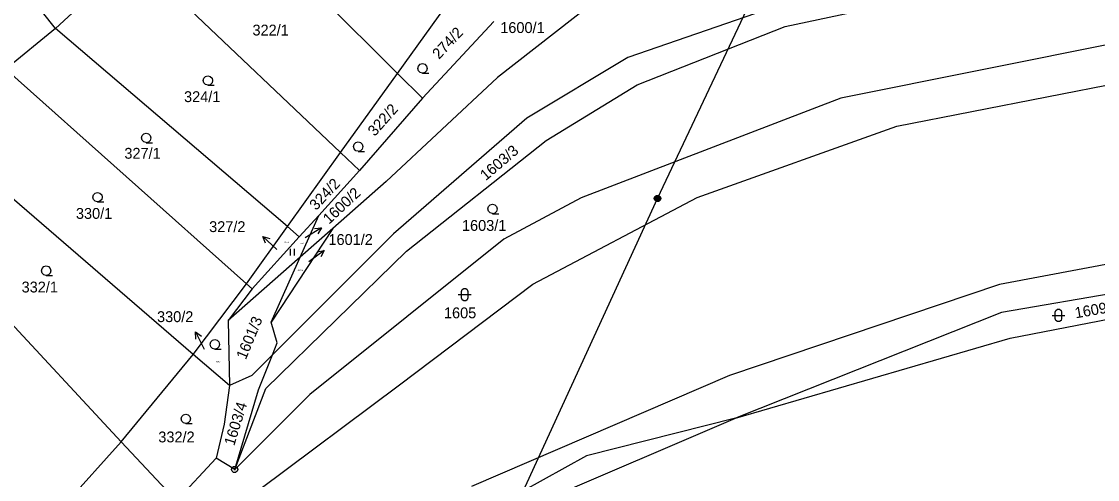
# Model space of a CAD drawing. Extents: x -609861 to -605046, y -1120287 to -1116307.
# Drawn here: x -607005 to -606836.4, y -1119419.2 to -1119347.5 of the extents above; entities that cross this region are included whole.
import ezdxf

# ---------------------------------------------------------------- set-up
doc = ezdxf.new("R2010")
doc.units = 0
for name, color, linetype in [('Vrstva 1', 7, 'Continuous'), ('Vrstva 2', 7, 'Continuous'), ('Vrstva 3', 7, 'Continuous'), ('Vrstva 6', 7, 'Continuous'), ('Vrstva 7', 7, 'Continuous'), ('Vrstva 8', 7, 'Continuous')]:
    doc.layers.add(name, color=color, linetype=linetype)

msp = doc.modelspace()

# ---------------------------------------------------------------- linework, layer by layer
at = {"layer": 'Vrstva 1'}
for p, q in [((-606946.12, -1119355.62), (-606977.36, -1119324.47)), ((-606955.04, -1119368.04), (-606988.81, -1119335.87)), ((-606989.19, -1119338.85), (-606999.69, -1119348.61)), ((-606885.36, -1119348.3), (-606850.68, -1119340.86)), ((-606999.69, -1119348.61), (-607004.74, -1119342.23)), ((-606946.12, -1119355.62), (-606935.93, -1119341.43)), ((-606915.48, -1119344.63), (-606930.45, -1119356.29)), ((-606888.5, -1119345.74), (-606910.04, -1119353.16)), ((-606931.04, -1119347.49), (-606942.21, -1119359.52)), ((-606999.69, -1119348.61), (-607007.45, -1119354.95)), ((-606963.35, -1119379.63), (-606999.69, -1119348.61)), ((-606908.56, -1119357.42), (-606885.36, -1119348.3)), ((-606831.75, -1119350.51), (-606876.64, -1119359.5)), ((-606910.04, -1119353.16), (-606925.84, -1119362.66)), ((-606969.76, -1119388.57), (-607007.45, -1119354.95)), ((-606955.04, -1119368.04), (-606946.12, -1119355.62)), ((-606942.21, -1119359.52), (-606946.12, -1119355.62)), ((-606930.45, -1119356.29), (-606947.9, -1119372.58)), ((-606922.81, -1119366.13), (-606908.56, -1119357.42)), ((-606867.87, -1119363.9), (-606830.79, -1119356.66)), ((-606942.21, -1119359.52), (-606952.08, -1119370.86)), ((-606876.64, -1119359.5), (-606917.32, -1119375.11)), ((-606925.84, -1119362.66), (-606946.75, -1119380.73)), ((-606899.18, -1119375.06), (-606867.87, -1119363.9)), ((-606978.11, -1119399.64), (-607018.21, -1119365.11)), ((-606944.72, -1119383.49), (-606922.81, -1119366.13)), ((-606963.35, -1119379.63), (-606955.04, -1119368.04)), ((-606952.08, -1119370.86), (-606955.04, -1119368.04)), ((-606952.08, -1119370.86), (-606958.46, -1119377.87)), ((-606947.9, -1119372.58), (-606956.23, -1119379.91)), ((-606989.38, -1119413.31), (-607025.73, -1119374.26)), ((-606917.32, -1119375.11), (-606929.46, -1119381.58)), ((-606924.91, -1119388.66), (-606899.18, -1119375.06)), ((-606958.46, -1119377.87), (-606961.5, -1119381.2)), ((-606961.37, -1119384.43), (-606958.46, -1119377.87)), ((-606969.76, -1119388.57), (-606963.35, -1119379.63)), ((-606961.5, -1119381.2), (-606963.35, -1119379.63)), ((-606801.93, -1119379.31), (-606851.78, -1119388.68)), ((-606961.5, -1119381.2), (-606968.89, -1119389.35)), ((-606956.23, -1119379.91), (-606965.88, -1119394.61)), ((-606946.75, -1119380.73), (-606965.7, -1119399.71)), ((-606956.23, -1119379.91), (-606961.37, -1119384.43)), ((-606929.46, -1119381.58), (-606959.85, -1119405.9)), ((-606961.37, -1119384.43), (-606972.62, -1119394.33)), ((-606966.74, -1119404.96), (-606944.72, -1119383.49)), ((-606965.88, -1119394.61), (-606961.37, -1119384.43)), ((-606812.23, -1119386.28), (-606851.48, -1119393.09)), ((-606850.14, -1119397.08), (-606796.64, -1119386.74)), ((-606978.11, -1119399.64), (-606969.76, -1119388.57)), ((-606968.89, -1119389.35), (-606972.62, -1119394.33)), ((-606968.89, -1119389.35), (-606969.76, -1119388.57)), ((-606945.8, -1119404.38), (-606924.91, -1119388.66)), ((-606851.78, -1119388.68), (-606894.11, -1119402.92)), ((-606851.48, -1119393.09), (-606893.15, -1119409.63)), ((-606972.62, -1119394.33), (-606972.44, -1119404.52)), ((-606964.95, -1119397.81), (-606965.88, -1119394.61)), ((-606965.7, -1119399.71), (-606964.95, -1119397.81)), ((-606893.15, -1119409.63), (-606850.14, -1119397.08)), ((-606989.38, -1119413.31), (-606978.11, -1119399.64)), ((-606972.44, -1119404.52), (-606978.11, -1119399.64)), ((-606965.7, -1119399.71), (-606968.93, -1119402.94)), ((-606967.87, -1119405.18), (-606965.7, -1119399.71)), ((-606968.93, -1119402.94), (-606972.44, -1119404.52)), ((-606894.11, -1119402.92), (-606934.5, -1119420.33)), ((-606972.44, -1119404.52), (-606973.28, -1119410.57)), ((-606967.9, -1119420.89), (-606945.8, -1119404.38)), ((-606971.62, -1119417.67), (-606966.74, -1119404.96)), ((-606971.62, -1119417.67), (-606967.87, -1119405.18)), ((-606959.85, -1119405.9), (-606971.62, -1119417.67)), ((-606923.77, -1119422.74), (-606893.15, -1119409.63)), ((-606893.15, -1119409.63), (-606916.49, -1119415.51)), ((-606973.28, -1119410.57), (-606974.51, -1119415.91)), ((-607001.13, -1119426.36), (-606989.38, -1119413.31)), ((-606980.75, -1119422.57), (-606989.38, -1119413.31)), ((-606974.51, -1119415.91), (-606980.75, -1119422.57)), ((-606971.62, -1119417.67), (-606974.51, -1119415.91)), ((-606916.49, -1119415.51), (-606965.86, -1119442.76))]:
    msp.add_line(p, q, dxfattribs=at)
at = {"layer": 'Vrstva 3'}
for p, q in [((-606962.94, -1119383.09), (-606962.94, -1119384.14)), ((-606962.24, -1119384.14), (-606962.24, -1119383.09))]:
    msp.add_line(p, q, dxfattribs=at)
for points in [[(-606942.18, -1119355.58), (-606942.56, -1119355.48), (-606942.83, -1119355.21), (-606942.93, -1119354.84), (-606942.83, -1119354.47), (-606942.56, -1119354.2), (-606942.19, -1119354.1), (-606941.82, -1119354.2), (-606941.55, -1119354.47), (-606941.45, -1119354.85), (-606941.55, -1119355.23), (-606941.82, -1119355.5), (-606942.2, -1119355.6), (-606941.2, -1119355.6)], [(-606975.8, -1119357.47), (-606976.18, -1119357.37), (-606976.45, -1119357.1), (-606976.55, -1119356.73), (-606976.45, -1119356.36), (-606976.18, -1119356.09), (-606975.81, -1119355.99), (-606975.44, -1119356.09), (-606975.17, -1119356.36), (-606975.07, -1119356.74), (-606975.17, -1119357.12), (-606975.44, -1119357.39), (-606975.82, -1119357.49), (-606974.82, -1119357.49)], [(-606985.49, -1119366.46), (-606985.87, -1119366.36), (-606986.14, -1119366.09), (-606986.24, -1119365.72), (-606986.14, -1119365.35), (-606985.87, -1119365.08), (-606985.5, -1119364.98), (-606985.13, -1119365.08), (-606984.86, -1119365.35), (-606984.76, -1119365.73), (-606984.86, -1119366.11), (-606985.13, -1119366.38), (-606985.51, -1119366.48), (-606984.51, -1119366.48)], [(-606952.25, -1119367.83), (-606952.63, -1119367.73), (-606952.9, -1119367.46), (-606953, -1119367.09), (-606952.9, -1119366.72), (-606952.63, -1119366.45), (-606952.26, -1119366.35), (-606951.89, -1119366.45), (-606951.62, -1119366.72), (-606951.52, -1119367.1), (-606951.62, -1119367.48), (-606951.89, -1119367.75), (-606952.27, -1119367.85), (-606951.27, -1119367.85)], [(-606993.09, -1119375.74), (-606993.47, -1119375.64), (-606993.74, -1119375.37), (-606993.84, -1119375), (-606993.74, -1119374.63), (-606993.47, -1119374.36), (-606993.1, -1119374.26), (-606992.73, -1119374.36), (-606992.46, -1119374.63), (-606992.36, -1119375.01), (-606992.46, -1119375.39), (-606992.73, -1119375.66), (-606993.11, -1119375.76), (-606992.11, -1119375.76)], [(-606931.22, -1119377.59), (-606931.6, -1119377.49), (-606931.87, -1119377.22), (-606931.97, -1119376.85), (-606931.87, -1119376.48), (-606931.6, -1119376.21), (-606931.23, -1119376.11), (-606930.86, -1119376.21), (-606930.59, -1119376.48), (-606930.49, -1119376.86), (-606930.59, -1119377.24), (-606930.86, -1119377.51), (-606931.24, -1119377.61), (-606930.24, -1119377.61)], [(-607001.14, -1119387.27), (-607001.52, -1119387.17), (-607001.79, -1119386.9), (-607001.89, -1119386.53), (-607001.79, -1119386.16), (-607001.52, -1119385.89), (-607001.15, -1119385.79), (-607000.78, -1119385.89), (-607000.51, -1119386.16), (-607000.41, -1119386.54), (-607000.51, -1119386.92), (-607000.78, -1119387.19), (-607001.16, -1119387.29), (-607000.16, -1119387.29)], [(-606936.58, -1119390.28), (-606935.31, -1119390.28), (-606934.58, -1119390.28)], [(-606843.56, -1119393.54), (-606842.29, -1119393.54), (-606841.56, -1119393.54)], [(-606974.71, -1119398.8), (-606975.09, -1119398.7), (-606975.36, -1119398.43), (-606975.46, -1119398.06), (-606975.36, -1119397.69), (-606975.09, -1119397.42), (-606974.72, -1119397.32), (-606974.35, -1119397.42), (-606974.08, -1119397.69), (-606973.98, -1119398.07), (-606974.08, -1119398.45), (-606974.35, -1119398.72), (-606974.73, -1119398.82), (-606973.73, -1119398.82)], [(-606979.27, -1119410.46), (-606979.65, -1119410.36), (-606979.92, -1119410.09), (-606980.02, -1119409.72), (-606979.92, -1119409.35), (-606979.65, -1119409.08), (-606979.28, -1119408.98), (-606978.91, -1119409.08), (-606978.64, -1119409.35), (-606978.54, -1119409.73), (-606978.64, -1119410.11), (-606978.91, -1119410.38), (-606979.29, -1119410.48), (-606978.29, -1119410.48)]]:
    msp.add_lwpolyline(points, dxfattribs=at)
for points in [[(-606936.08, -1119389.78), (-606935.98, -1119389.49), (-606935.73, -1119389.31), (-606935.42, -1119389.31), (-606935.17, -1119389.49), (-606935.07, -1119389.78), (-606935.07, -1119390.78), (-606935.17, -1119391.07), (-606935.42, -1119391.25), (-606935.73, -1119391.25), (-606935.98, -1119391.07), (-606936.08, -1119390.78)], [(-606843.06, -1119393.04), (-606842.96, -1119392.75), (-606842.71, -1119392.57), (-606842.4, -1119392.57), (-606842.15, -1119392.75), (-606842.05, -1119393.04), (-606842.05, -1119394.04), (-606842.15, -1119394.33), (-606842.4, -1119394.51), (-606842.71, -1119394.51), (-606842.96, -1119394.33), (-606843.06, -1119394.04)]]:
    msp.add_lwpolyline(points, close=True, dxfattribs=at)
at = {"layer": 'Vrstva 6'}
for p, q in [((-606905.37, -1119375.22), (-606885.51, -1119333.21)), ((-606927.27, -1119422.87), (-606905.37, -1119375.22))]:
    msp.add_line(p, q, dxfattribs=at)
msp.add_lwpolyline([(-606905.52, -1119374.74), (-606905.21, -1119374.74), (-606904.96, -1119374.92), (-606904.86, -1119375.21), (-606904.96, -1119375.5), (-606905.21, -1119375.68), (-606905.52, -1119375.68), (-606905.77, -1119375.5), (-606905.87, -1119375.21), (-606905.77, -1119374.92), (-606905.52, -1119374.74), (-606905.49, -1119374.78), (-606905.25, -1119374.78), (-606905.09, -1119374.86), (-606905.65, -1119374.86), (-606905.73, -1119374.94), (-606905.01, -1119374.94), (-606905.01, -1119375.02), (-606905.73, -1119375.02), (-606905.77, -1119375.1), (-606904.97, -1119375.1), (-606904.93, -1119375.18), (-606905.81, -1119375.18), (-606905.81, -1119375.26), (-606904.93, -1119375.26), (-606904.96, -1119375.34), (-606905.77, -1119375.34), (-606905.76, -1119375.42), (-606904.95, -1119375.42), (-606905, -1119375.5), (-606905.72, -1119375.5), (-606905.64, -1119375.58), (-606905.08, -1119375.58), (-606905.19, -1119375.66), (-606905.53, -1119375.66)], dxfattribs=at)
at = {"layer": 'Vrstva 7'}
for p, q in [((-606967.192, -1119381.152), (-606964.99, -1119383.19)), ((-606958.007, -1119379.795), (-606960.56, -1119381.37)), ((-606957.618, -1119383.352), (-606960.02, -1119385.15)), ((-606977.739, -1119396.125), (-606976.38, -1119398.8))]:
    msp.add_line(p, q, dxfattribs=at)
for points in [[(-606966.797, -1119382.198), (-606967.192, -1119381.152), (-606966.118, -1119381.464)], [(-606959.12, -1119379.895), (-606958.007, -1119379.795), (-606958.595, -1119380.746)], [(-606958.719, -1119383.551), (-606957.618, -1119383.352), (-606958.119, -1119384.352)], [(-606977.732, -1119397.243), (-606977.739, -1119396.125), (-606976.84, -1119396.79)]]:
    msp.add_lwpolyline(points, dxfattribs=at)
at = {"layer": 'Vrstva 8'}
msp.add_line((-606971.74, -1119417.67), (-606971.5, -1119417.67), dxfattribs=at)
msp.add_lwpolyline([(-606971.47, -1119417.19), (-606971.22, -1119417.37), (-606971.12, -1119417.66), (-606971.22, -1119417.95), (-606971.47, -1119418.13), (-606971.78, -1119418.13), (-606972.03, -1119417.95), (-606972.13, -1119417.66), (-606972.03, -1119417.37), (-606971.78, -1119417.19)], close=True, dxfattribs=at)

# ---------------------------------------------------------------- texts
at = {"layer": 'Vrstva 2'}
for s, height, p in [('1600/1', 1.7, (-606930.007, -1119349.3)), ('322/1', 1.7, (-606968.833, -1119349.69)), ('324/1', 1.7, (-606979.553, -1119360.12)), ('327/1', 1.7, (-606988.903, -1119368.99)), ('330/1', 1.7, (-606996.493, -1119378.41)), ('1603/1', 1.7, (-606936.007, -1119380.29)), ('327/2', 0.2, (-606963.842, -1119382.17)), ('1600/2', 0.2, (-606961.574, -1119382.37)), ('1601/2', 0.2, (-606961.764, -1119386.57)), ('332/1', 1.7, (-607005.003, -1119389.94)), ('1605', 1.7, (-606938.827, -1119393.98)), ('330/2', 0.2, (-606974.532, -1119400.9)), ('332/2', 1.7, (-606983.583, -1119413.42))]:
    msp.add_text(s, height=height, dxfattribs=at).set_placement(p)
for s, rotation, p in [('274/2', 46.81065, (-606939.598, -1119353.507)), ('322/2', 48.58682, (-606949.663, -1119365.582)), ('1603/3', 40.50812, (-606932.271, -1119372.505)), ('324/2', 46.81065, (-606958.858, -1119377.187)), ('1609/3', 9.91217, (-606839.833, -1119393.992)), ('1601/3', 67.49443, (-606969.88, -1119400.567)), ('1603/4', 72.88023, (-606971.694, -1119414.055))]:
    msp.add_text(s, height=1.7, rotation=rotation, dxfattribs=at).set_placement(p)
at = {"layer": 'Vrstva 7'}
msp.add_text('1600/2', height=1.7, rotation=43.20102, dxfattribs=at).set_placement((-606956.824, -1119379.331))
for s, p in [('327/2', (-606975.623, -1119380.48)), ('1601/2', (-606956.927, -1119382.5)), ('330/2', (-606983.783, -1119394.58))]:
    msp.add_text(s, height=1.7, dxfattribs=at).set_placement(p)

doc.saveas('drawing.dxf')
